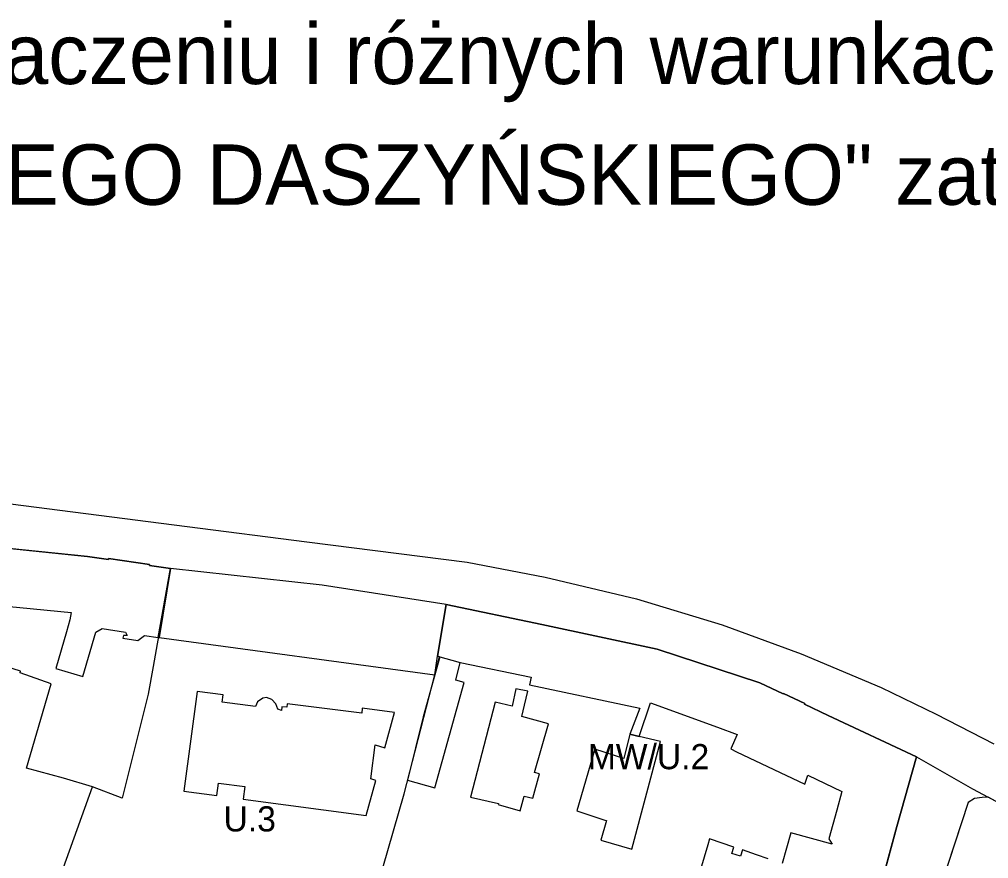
# Model space of a CAD drawing. Extents: x 7424052 to 7425705, y 5546602 to 5547569.
# Drawn here: x 7424972 to 7425164.6, y 5547402.5 to 5547569.3 of the extents above; entities that cross this region are included whole.
import ezdxf

# ---------------------------------------------------------------- set-up
doc = ezdxf.new("R2010")
doc.units = 0
for name, color, linetype in [('info', 7, 'Continuous'), ('linie rozgraniczające', 7, 'Continuous'), ('nieprzekraczalne linie zabudowy', 7, 'Continuous'), ('obowiazujace linie zabudowy', 7, 'Continuous'), ('przeznaczenia terenów', 7, 'Continuous')]:
    doc.layers.add(name, color=color, linetype=linetype)

msp = doc.modelspace()

# ---------------------------------------------------------------- linework, layer by layer
at = {"layer": 'linie rozgraniczające'}
for p, q in [((7424954.69, 5547474.96), (7425005.28, 5547468.49)), ((7425005.28, 5547468.49), (7425029.1, 5547465.45)), ((7424963.39, 5547464.82), (7424985.51, 5547462.54)), ((7425029.1, 5547465.45), (7425060.93, 5547461.39)), ((7424985.51, 5547462.54), (7424989.66, 5547461.94)), ((7424989.66, 5547461.94), (7424989.69, 5547462.14)), ((7424989.69, 5547462.14), (7424997.82, 5547460.98)), ((7424997.82, 5547460.98), (7424997.79, 5547460.77)), ((7424997.79, 5547460.77), (7425002.02, 5547460.16)), ((7425002.02, 5547460.16), (7424998.55, 5547440.7)), ((7425032.16, 5547456.85), (7425002.02, 5547460.16)), ((7425060.93, 5547461.39), (7425076.47, 5547458.43)), ((7425076.47, 5547458.43), (7425094.59, 5547454.1)), ((7425056.79, 5547452.97), (7425032.16, 5547456.85)), ((7425094.59, 5547454.1), (7425111.65, 5547448.94)), ((7425055.31, 5547444.16), (7425056.72, 5547452.63)), ((7425056.72, 5547452.63), (7425056.79, 5547452.97)), ((7425056.79, 5547452.97), (7425075.8, 5547449.02)), ((7425075.8, 5547449.02), (7425098.73, 5547444.12)), ((7425111.65, 5547448.94), (7425127.35, 5547443.2)), ((7424972.19, 5547439.75), (7424956.07, 5547444.88)), ((7425054.49, 5547439), (7425055.45, 5547442.62)), ((7425055.07, 5547442.71), (7425055.31, 5547444.16)), ((7425055.45, 5547442.62), (7425055.07, 5547442.71)), ((7425098.73, 5547444.12), (7425119.09, 5547437.43)), ((7425127.35, 5547443.2), (7425143.23, 5547436.52)), ((7424998.55, 5547440.7), (7424997.56, 5547435.2)), ((7424972.09, 5547439.42), (7424972.19, 5547439.75)), ((7424978.28, 5547437.26), (7424972.09, 5547439.42)), ((7425048.43, 5547415.4), (7425054.49, 5547439)), ((7424973.36, 5547420.46), (7424978.28, 5547437.26)), ((7425119.09, 5547437.43), (7425123.74, 5547435.22)), ((7424997.56, 5547435.2), (7424992.37, 5547414.51)), ((7425123.74, 5547435.22), (7425123.8, 5547435.32)), ((7425123.8, 5547435.32), (7425128.03, 5547433.3)), ((7425143.23, 5547436.52), (7425154.13, 5547431.2)), ((7425128.03, 5547433.3), (7425128, 5547433.19)), ((7425128, 5547433.19), (7425132.66, 5547430.97)), ((7425132.66, 5547430.97), (7425150.24, 5547422.7)), ((7425154.13, 5547431.2), (7425165.61, 5547425.28)), ((7425150.24, 5547422.7), (7425146.34, 5547408.9)), ((7425150.24, 5547422.7), (7425161.39, 5547416.36)), ((7424980.75, 5547418.49), (7424973.36, 5547420.46)), ((7424986.52, 5547416.78), (7424980.75, 5547418.49)), ((7424979.78, 5547398.16), (7424986.52, 5547416.78)), ((7424992.37, 5547414.51), (7424986.52, 5547416.78)), ((7425044.17, 5547400.66), (7425048.43, 5547415.4)), ((7425161.39, 5547416.36), (7425164.46, 5547414.7)), ((7425160.51, 5547413.68), (7425153.59, 5547392.63)), ((7425161.76, 5547414.44), (7425160.51, 5547413.68)), ((7425163.28, 5547414.67), (7425161.76, 5547414.44)), ((7425164.46, 5547414.7), (7425163.28, 5547414.67)), ((7425172.57, 5547410.31), (7425164.46, 5547414.7)), ((7425146.34, 5547408.9), (7425142.58, 5547394.99))]:
    msp.add_line(p, q, dxfattribs=at)
at = {"layer": 'nieprzekraczalne linie zabudowy'}
for p, q in [((7425002.02, 5547460.16), (7424999.72, 5547446.41)), ((7425055.07, 5547442.71), (7425056.79, 5547452.97)), ((7424999.72, 5547446.41), (7425054.49, 5547439)), ((7425054.49, 5547439), (7425055.07, 5547442.71)), ((7425055.48, 5547442.62), (7425054.49, 5547439)), ((7425058.67, 5547437.96), (7425059.58, 5547441.48)), ((7425054.49, 5547439), (7425052.2, 5547430.69)), ((7425054.55, 5547416.56), (7425060.37, 5547437.5)), ((7425060.37, 5547437.5), (7425058.67, 5547437.96)), ((7425070.62, 5547436.25), (7425069.91, 5547432.82)), ((7425073.01, 5547435.75), (7425070.62, 5547436.25)), ((7425072.68, 5547434.37), (7425073.01, 5547435.75)), ((7425066.53, 5547433.62), (7425061.6, 5547414.72)), ((7425069.91, 5547432.82), (7425066.53, 5547433.62)), ((7425071.81, 5547430.76), (7425072.35, 5547433)), ((7425072.35, 5547433), (7425072.68, 5547434.37)), ((7425052.2, 5547430.69), (7425049.12, 5547418.1)), ((7425077.11, 5547429.3), (7425071.81, 5547430.76)), ((7425074.34, 5547419.59), (7425077.11, 5547429.3)), ((7425093.28, 5547427.22), (7425092.07, 5547422.39)), ((7425095.15, 5547426.77), (7425093.28, 5547427.22)), ((7425093.65, 5547404.35), (7425099.36, 5547425.77)), ((7425099.36, 5547425.77), (7425095.15, 5547426.77)), ((7425086.34, 5547424.27), (7425082.75, 5547411.98)), ((7425092.07, 5547422.39), (7425086.34, 5547424.27)), ((7425074.02, 5547414.5), (7425075.31, 5547419.33)), ((7425075.31, 5547419.33), (7425074.34, 5547419.59)), ((7425049.12, 5547418.1), (7425054.55, 5547416.56)), ((7425061.6, 5547414.72), (7425067.16, 5547413.43)), ((7425071.47, 5547412.01), (7425072.28, 5547414.91)), ((7425072.28, 5547414.91), (7425074.02, 5547414.5)), ((7425067.16, 5547413.43), (7425067.11, 5547413.23)), ((7425067.11, 5547413.23), (7425071.47, 5547412.01)), ((7425082.75, 5547411.98), (7425088.28, 5547410.17)), ((7425088.62, 5547410.09), (7425087.52, 5547406.18)), ((7425088.28, 5547410.17), (7425088.62, 5547410.09)), ((7425087.52, 5547406.18), (7425093.65, 5547404.35))]:
    msp.add_line(p, q, dxfattribs=at)
at = {"layer": 'obowiazujace linie zabudowy'}
for points in [[(7424999.57, 5547446.43), (7425002.02, 5547460.16), (7424997.79, 5547460.77), (7424997.82, 5547460.98), (7424989.69, 5547462.14), (7424989.66, 5547461.94), (7424985.51, 5547462.54), (7424963.39, 5547464.82), (7424961.8, 5547453.38), (7424982.24, 5547451.4), (7424981.99, 5547449.94), (7424981.3, 5547447.56), (7424979.18, 5547440.31), (7424984.6, 5547438.67), (7424987.18, 5547447.5), (7424988.38, 5547448.26), (7424993.08, 5547447.53), (7424993.35, 5547446.81), (7424992.63, 5547446.87), (7424992.52, 5547446.31), (7424995.47, 5547445.82), (7424996.85, 5547446.85), (7424999.57, 5547446.43)], [(7425056.79, 5547452.97), (7425032.16, 5547456.85), (7425002.02, 5547460.16)], [(7425142.58, 5547394.99), (7425146.34, 5547408.9), (7425150.24, 5547422.7), (7425132.66, 5547430.97), (7425128, 5547433.19), (7425128.03, 5547433.3), (7425123.8, 5547435.32), (7425123.74, 5547435.22), (7425119.09, 5547437.43), (7425098.73, 5547444.12), (7425075.8, 5547449.02), (7425056.79, 5547452.97), (7425055.07, 5547442.71), (7425059.58, 5547441.48), (7425073.64, 5547438.59), (7425073.33, 5547437.06), (7425095.26, 5547432.41), (7425093.28, 5547427.22), (7425095.15, 5547426.77), (7425095.15, 5547426.77), (7425097.37, 5547433.48), (7425110.69, 5547428.64), (7425114.63, 5547427.2), (7425113.37, 5547424.31), (7425114.44, 5547423.73), (7425128.02, 5547417.29), (7425128.62, 5547419.07), (7425135.4, 5547415.87), (7425134.41, 5547412.15), (7425132.82, 5547406.43), (7425133.48, 5547405.4), (7425125.26, 5547407.61), (7425123.52, 5547401.54)], [(7425007.26, 5547435.68), (7425004.64, 5547415.89), (7425011.17, 5547415.02), (7425011.55, 5547417.53), (7425016.76, 5547416.86), (7425016.45, 5547414.32), (7425040.87, 5547411.07), (7425042.8, 5547418.05), (7425041.79, 5547418.39), (7425042.69, 5547425.13), (7425044.61, 5547424.55), (7425046.52, 5547431.52), (7425040.11, 5547432.4), (7425040.02, 5547431.43), (7425025.18, 5547433.24), (7425025.11, 5547432.59), (7425024.14, 5547432.68), (7425024.07, 5547431.96), (7425023.29, 5547432.17), (7425022.95, 5547433.29), (7425022.14, 5547434.14), (7425021.06, 5547434.49), (7425020.31, 5547434.37), (7425019.27, 5547433.67), (7425018.86, 5547432.71), (7425012.25, 5547433.59), (7425012.47, 5547435.03), (7425007.26, 5547435.68)], [(7425172.57, 5547410.31), (7425164.46, 5547414.7), (7425163.28, 5547414.67), (7425161.76, 5547414.44), (7425160.51, 5547413.68), (7425153.59, 5547392.63)], [(7425120.78, 5547402.47), (7425118.47, 5547403.26), (7425115.63, 5547404.23), (7425115.25, 5547402.96), (7425113.56, 5547403.53), (7425113.96, 5547404.8), (7425109.11, 5547406.46), (7425108.75, 5547405.23), (7425107.33, 5547400.34)]]:
    msp.add_lwpolyline(points, dxfattribs=at)

# ---------------------------------------------------------------- texts
at = {"layer": 'info'}
for s, p in [('Materiał pomocniczy zawierający linie rozgraniczające teren o różnym przeznaczeniu i różnych warunkach zagospodarowania terenu, ', (7424420.28, 5547556.42)), ('opracowane w skali 1:1000 pochodzące z Miejscowego Planu Zagospodarowania Przestrzennego obszaru "REJON ALEI IGNACEGO DASZYŃSKIEGO" zatwierdzonego uchwałą RMK Nr CXIV/3010/18 z dnia 24 października 2018 r.', (7424050.89, 5547532.42))]:
    msp.add_text(s, height=12, dxfattribs=at).set_placement(p)
at = {"layer": 'przeznaczenia terenów'}
for s, p in [('MW/U.2', (7425084.91, 5547420.27)), ('U.3', (7425012.53, 5547407.9))]:
    msp.add_text(s, height=5, dxfattribs=at).set_placement(p)

doc.saveas('drawing.dxf')
